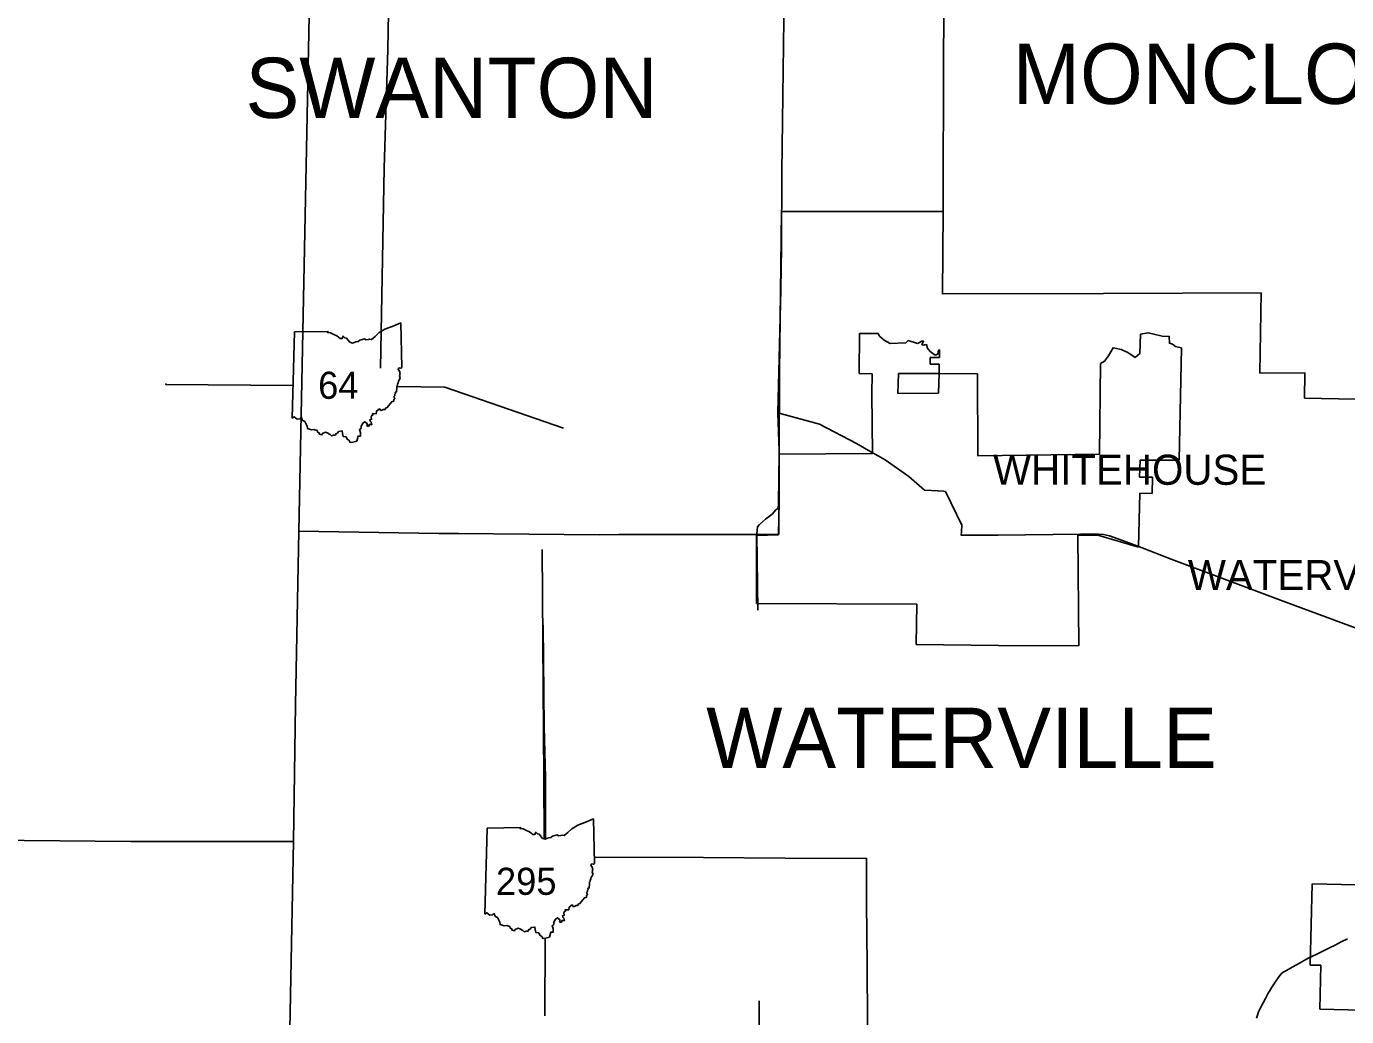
# Model space of a CAD drawing. Extents: x -232 to 448, y 619 to 1059.
# Drawn here: x 68.14 to 113.08, y 864.09 to 897.81 of the extents above; entities that cross this region are included whole.
import ezdxf

# ---------------------------------------------------------------- set-up
doc = ezdxf.new("R2010")
doc.units = 0
doc.layers.add('Default', color=7, linetype='Continuous')

msp = doc.modelspace()

# ---------------------------------------------------------------- linework, layer by layer
at = {"layer": 'Default'}
for p, q in [((77.184, 884.471), (77.266, 887.4)), ((77.184, 884.471), (77.266, 887.4)), ((96.497, 887.343), (96.48, 885.992)), ((97.134, 887.343), (96.497, 887.343)), ((97.182, 887.256), (97.134, 887.343)), ((97.333, 887.121), (97.182, 887.256)), ((97.543, 887.007), (97.333, 887.121)), ((98.155, 887.111), (98.071, 887.035)), ((98.471, 887.009), (98.155, 887.111)), ((98.615, 887.092), (98.471, 887.009)), ((98.678, 887.102), (98.615, 887.092)), ((98.622, 886.958), (98.678, 887.102)), ((98.071, 887.035), (97.543, 887.007)), ((98.681, 886.948), (98.622, 886.958)), ((98.752, 886.97), (98.681, 886.948)), ((98.793, 886.961), (98.752, 886.97)), ((98.801, 886.864), (98.793, 886.961)), ((98.9, 886.735), (98.801, 886.864)), ((99.034, 886.628), (98.9, 886.735)), ((99.085, 886.611), (99.034, 886.628)), ((99.173, 886.651), (99.085, 886.611)), ((99.175, 886.733), (99.173, 886.651)), ((99.223, 886.801), (99.175, 886.733)), ((99.216, 886.535), (99.223, 886.801)), ((98.906, 886.534), (99.216, 886.535)), ((98.906, 886.3), (98.906, 886.534)), ((99.211, 886.3), (98.906, 886.3)), ((99.204, 885.991), (99.211, 886.3)), ((106.469, 882.452), (106.026, 882.454)), ((106.454, 881.901), (106.469, 882.452)), ((106.035, 881.914), (106.454, 881.901)), ((83.743, 867.581), (83.825, 870.51)), ((83.743, 867.581), (83.825, 870.51)), ((111.904, 868.613), (111.837, 865.843)), ((113.904, 868.564), (111.904, 868.613)), ((111.837, 865.843), (112.196, 865.835)), ((112.196, 865.835), (112.16, 864.343)), ((112.16, 864.343), (116.541, 864.237))]:
    msp.add_line(p, q, dxfattribs=at)
for points in [[(99.344, 891.498), (99.352, 896.947), (99.427, 902.322), (99.435, 907.773), (99.476, 913.158)], [(77.412, 880.616), (77.896, 904.964), (77.947, 907.809)], [(93.721, 884.643), (93.821, 888.838), (93.84, 890.285), (93.853, 892.85), (93.98, 902.356)], [(80.187, 886.165), (80.321, 892.983), (80.445, 897.015), (80.493, 899.517)], [(93, 880.507), (93.754, 880.517), (93.773, 886.025), (93.847, 891.503), (99.344, 891.498)], [(127.784, 884.833), (111.649, 885.151), (111.657, 885.999), (110.121, 886.009), (110.165, 888.733), (104.807, 888.708), (99.321, 888.696), (99.344, 891.498)], [(77.266, 887.4), (78.402, 887.419), (78.385, 887.383), (78.492, 887.376), (78.606, 887.313), (78.702, 887.274), (78.82, 887.181), (78.891, 887.182), (78.92, 887.258), (78.974, 887.199), (79.038, 887.189), (79.149, 887.048), (79.241, 887.018), (79.35, 887.066), (79.432, 887.074), (79.492, 887.121), (79.648, 887.162), (79.691, 887.138), (79.774, 887.143), (79.815, 887.161), (79.887, 887.145), (80.014, 887.251), (80.145, 887.377), (80.345, 887.495), (80.645, 887.607), (80.882, 887.708), (80.916, 886.188)], [(77.266, 887.4), (78.402, 887.419), (78.385, 887.383), (78.492, 887.376), (78.606, 887.313), (78.702, 887.274), (78.82, 887.181), (78.891, 887.182), (78.92, 887.258), (78.974, 887.199), (79.038, 887.189), (79.149, 887.048), (79.241, 887.018), (79.35, 887.066), (79.432, 887.074), (79.492, 887.121), (79.648, 887.162), (79.691, 887.138), (79.774, 887.143), (79.815, 887.161), (79.887, 887.145), (80.014, 887.251), (80.145, 887.377), (80.345, 887.495), (80.645, 887.607), (80.882, 887.708), (80.916, 886.188)], [(107.461, 886.861), (107.256, 886.902), (107.146, 886.983), (107.046, 887.019), (107.04, 887.252), (106.794, 887.26), (106.516, 887.33), (106.317, 887.373), (106.06, 887.324), (106.038, 886.664), (105.885, 886.53)], [(105.885, 886.53), (105.634, 886.7), (105.399, 886.805), (105.128, 886.865), (104.968, 886.584), (104.833, 886.407), (104.697, 886.322), (104.671, 883.236)], [(106.026, 882.454), (106.046, 883.035), (107.377, 883.036), (107.461, 886.861)], [(80.916, 886.188), (80.881, 886.166), (80.827, 886.176), (80.79, 886.134), (80.836, 886.063), (80.857, 885.988), (80.838, 885.905), (80.857, 885.836), (80.844, 885.779), (80.81, 885.722), (80.798, 885.668), (80.769, 885.611), (80.771, 885.579), (80.744, 885.554), (80.749, 885.459), (80.735, 885.406), (80.739, 885.36), (80.694, 885.349), (80.705, 885.311), (80.676, 885.282), (80.682, 885.232), (80.65, 885.2), (80.681, 885.136), (80.656, 885.116), (80.635, 885.039), (80.577, 885.023), (80.462, 884.881), (80.421, 884.828), (80.375, 884.814), (80.35, 884.759), (80.294, 884.759), (80.208, 884.721), (80.153, 884.786), (80.056, 884.707), (80.045, 884.616), (79.923, 884.619), (79.928, 884.573), (79.9, 884.559), (79.875, 884.513), (79.89, 884.431), (79.833, 884.41), (79.84, 884.362), (79.876, 884.333), (79.893, 884.242), (79.832, 884.26), (79.782, 884.183), (79.731, 884.201), (79.747, 884.267), (79.661, 884.345), (79.579, 884.282), (79.536, 884.182), (79.536, 884.114), (79.475, 884.074), (79.514, 883.978), (79.507, 883.913), (79.508, 883.851), (79.432, 883.853), (79.385, 883.685)], [(80.916, 886.188), (80.881, 886.166), (80.827, 886.176), (80.79, 886.134), (80.836, 886.063), (80.857, 885.988), (80.838, 885.905), (80.857, 885.836), (80.844, 885.779), (80.81, 885.722), (80.798, 885.668), (80.769, 885.611), (80.771, 885.579), (80.744, 885.554), (80.749, 885.459), (80.735, 885.406), (80.739, 885.36), (80.694, 885.349), (80.705, 885.311), (80.676, 885.282), (80.682, 885.232), (80.65, 885.2), (80.681, 885.136), (80.656, 885.116), (80.635, 885.039), (80.577, 885.023), (80.462, 884.881), (80.421, 884.828), (80.375, 884.814), (80.35, 884.759), (80.294, 884.759), (80.208, 884.721), (80.153, 884.786), (80.056, 884.707), (80.045, 884.616), (79.923, 884.619), (79.928, 884.573), (79.9, 884.559), (79.875, 884.513), (79.89, 884.431), (79.833, 884.41), (79.84, 884.362), (79.876, 884.333), (79.893, 884.242), (79.832, 884.26), (79.782, 884.183), (79.731, 884.201), (79.747, 884.267), (79.661, 884.345), (79.579, 884.282), (79.536, 884.182), (79.536, 884.114), (79.475, 884.074), (79.514, 883.978), (79.507, 883.913), (79.508, 883.851), (79.432, 883.853), (79.385, 883.685)], [(96.48, 885.992), (96.929, 885.978)], [(96.929, 885.978), (96.913, 885.298)], [(97.819, 885.992), (97.801, 885.302)], [(99.204, 885.991), (97.819, 885.992)], [(99.187, 885.314), (99.204, 885.991)], [(104.671, 883.236), (100.522, 883.187), (100.51, 885.97), (99.204, 885.991)], [(77.215, 885.583), (72.885, 885.616), (72.885, 885.648)], [(86.42, 884.126), (82.381, 885.518), (80.744, 885.541)], [(96.913, 885.298), (96.935, 883.259)], [(97.801, 885.302), (99.187, 885.314)], [(79.385, 883.685), (79.253, 883.652), (79.161, 883.633), (79.128, 883.71), (79.062, 883.75), (79.02, 883.827), (78.925, 883.837), (78.903, 883.943), (78.892, 884.029), (78.763, 884.007), (78.727, 883.955), (78.682, 883.941), (78.655, 883.888), (78.592, 883.884), (78.525, 883.859), (78.482, 883.911), (78.372, 883.963), (78.322, 883.989), (78.219, 883.948), (78.197, 883.898), (78.115, 883.92), (78.096, 883.975), (78.046, 883.992), (78.035, 884.05), (77.928, 884.081), (77.847, 884.069), (77.704, 884.116), (77.695, 884.192), (77.646, 884.286), (77.621, 884.351), (77.53, 884.401), (77.511, 884.478), (77.482, 884.475), (77.456, 884.444), (77.355, 884.43), (77.315, 884.461), (77.259, 884.515), (77.184, 884.471)], [(79.385, 883.685), (79.253, 883.652), (79.161, 883.633), (79.128, 883.71), (79.062, 883.75), (79.02, 883.827), (78.925, 883.837), (78.903, 883.943), (78.892, 884.029), (78.763, 884.007), (78.727, 883.955), (78.682, 883.941), (78.655, 883.888), (78.592, 883.884), (78.525, 883.859), (78.482, 883.911), (78.372, 883.963), (78.322, 883.989), (78.219, 883.948), (78.197, 883.898), (78.115, 883.92), (78.096, 883.975), (78.046, 883.992), (78.035, 884.05), (77.928, 884.081), (77.847, 884.069), (77.704, 884.116), (77.695, 884.192), (77.646, 884.286), (77.621, 884.351), (77.53, 884.401), (77.511, 884.478), (77.482, 884.475), (77.456, 884.444), (77.355, 884.43), (77.315, 884.461), (77.259, 884.515), (77.184, 884.471)], [(96.802, 883.37), (96.396, 883.599), (95.133, 884.263), (93.721, 884.643)], [(93.762, 883.348), (93.721, 884.643)], [(93.736, 881.561), (93.764, 883.283), (93.762, 883.348)], [(93.766, 883.238), (93.759, 881.618), (93.736, 880.493)], [(96.935, 883.259), (93.766, 883.238)], [(97.132, 883.184), (96.802, 883.37)], [(99.362, 881.975), (99.158, 881.986), (99.176, 881.989), (98.712, 882.01), (98.172, 882.478), (97.368, 883.051), (97.132, 883.184)], [(99.963, 880.6), (99.982, 880.821), (99.423, 881.972), (99.362, 881.975)], [(105.99, 880.072), (106.035, 881.914)], [(93.004, 880.527), (93.008, 880.652), (93.029, 880.761), (93.094, 880.848), (93.293, 881.029), (93.522, 881.199), (93.647, 881.341), (93.733, 881.404), (93.736, 881.561)], [(77.226, 870.052), (77.294, 874.706), (77.412, 880.616)], [(77.412, 880.616), (82.177, 880.541), (82.845, 880.535), (87.636, 880.498), (88.301, 880.5), (93, 880.507)], [(93.736, 880.493), (92.989, 880.471), (92.995, 878.151)], [(93.033, 877.931), (93.004, 880.5), (93.004, 880.527)], [(104.015, 880.512), (101.219, 880.484), (99.953, 880.484), (99.963, 880.6)], [(103.957, 876.714), (103.924, 880.479), (104.607, 880.485)], [(106.119, 880.048), (105.579, 880.258), (105.003, 880.454), (104.801, 880.501), (104.627, 880.518), (104.015, 880.512)], [(104.607, 880.485), (105.99, 880.072)], [(85.767, 870.139), (85.756, 872.214), (85.699, 879.99)], [(115.438, 876.56), (114.537, 876.899), (111.009, 878.195), (107.105, 879.666), (106.119, 880.048)], [(92.995, 878.151), (98.443, 878.129), (98.426, 876.757)], [(85.805, 870.139), (85.811, 872.224), (85.764, 873.967), (85.745, 876.224), (85.732, 877.414)], [(98.426, 876.757), (101.224, 876.723), (103.957, 876.714)], [(83.825, 870.51), (84.961, 870.529), (84.943, 870.493), (85.051, 870.486), (85.164, 870.423), (85.261, 870.384), (85.379, 870.291), (85.449, 870.292), (85.479, 870.368), (85.533, 870.309), (85.597, 870.299), (85.708, 870.158), (85.799, 870.128), (85.909, 870.176), (85.991, 870.184), (86.05, 870.232), (86.206, 870.272), (86.25, 870.248), (86.332, 870.253), (86.374, 870.271), (86.446, 870.255), (86.573, 870.361), (86.703, 870.487), (86.904, 870.605), (87.204, 870.717), (87.441, 870.818), (87.475, 869.298)], [(83.825, 870.51), (84.961, 870.529), (84.943, 870.493), (85.051, 870.486), (85.164, 870.423), (85.261, 870.384), (85.379, 870.291), (85.449, 870.292), (85.479, 870.368), (85.533, 870.309), (85.597, 870.299), (85.708, 870.158), (85.799, 870.128), (85.909, 870.176), (85.991, 870.184), (86.05, 870.232), (86.206, 870.272), (86.25, 870.248), (86.332, 870.253), (86.374, 870.271), (86.446, 870.255), (86.573, 870.361), (86.703, 870.487), (86.904, 870.605), (87.204, 870.717), (87.441, 870.818), (87.475, 869.298)], [(44.577, 870.248), (49.918, 870.254), (71.698, 870.05), (77.226, 870.052)], [(76.671, 842.765), (76.826, 849.139), (77.226, 870.052)], [(87.475, 869.298), (87.44, 869.277), (87.386, 869.287), (87.349, 869.244), (87.394, 869.173), (87.416, 869.098), (87.397, 869.015), (87.415, 868.947), (87.403, 868.889), (87.368, 868.833), (87.357, 868.778), (87.328, 868.721), (87.33, 868.689), (87.302, 868.664), (87.307, 868.569), (87.293, 868.516), (87.298, 868.471), (87.253, 868.459), (87.263, 868.421), (87.235, 868.392), (87.241, 868.342), (87.208, 868.31), (87.24, 868.247), (87.215, 868.226), (87.194, 868.149), (87.136, 868.133), (87.02, 867.991), (86.98, 867.938), (86.934, 867.924), (86.908, 867.869), (86.852, 867.869), (86.767, 867.831), (86.712, 867.897), (86.615, 867.817), (86.604, 867.726), (86.481, 867.729), (86.486, 867.683), (86.459, 867.669), (86.434, 867.623), (86.449, 867.541), (86.391, 867.52), (86.398, 867.472), (86.435, 867.443), (86.451, 867.352), (86.39, 867.37), (86.34, 867.294), (86.289, 867.312), (86.306, 867.377), (86.219, 867.455), (86.138, 867.392), (86.095, 867.292), (86.094, 867.225), (86.033, 867.184), (86.072, 867.089), (86.065, 867.023), (86.067, 866.961), (85.99, 866.963), (85.944, 866.795)], [(87.475, 869.298), (87.44, 869.277), (87.386, 869.287), (87.349, 869.244), (87.394, 869.173), (87.416, 869.098), (87.397, 869.015), (87.415, 868.947), (87.403, 868.889), (87.368, 868.833), (87.357, 868.778), (87.328, 868.721), (87.33, 868.689), (87.302, 868.664), (87.307, 868.569), (87.293, 868.516), (87.298, 868.471), (87.253, 868.459), (87.263, 868.421), (87.235, 868.392), (87.241, 868.342), (87.208, 868.31), (87.24, 868.247), (87.215, 868.226), (87.194, 868.149), (87.136, 868.133), (87.02, 867.991), (86.98, 867.938), (86.934, 867.924), (86.908, 867.869), (86.852, 867.869), (86.767, 867.831), (86.712, 867.897), (86.615, 867.817), (86.604, 867.726), (86.481, 867.729), (86.486, 867.683), (86.459, 867.669), (86.434, 867.623), (86.449, 867.541), (86.391, 867.52), (86.398, 867.472), (86.435, 867.443), (86.451, 867.352), (86.39, 867.37), (86.34, 867.294), (86.289, 867.312), (86.306, 867.377), (86.219, 867.455), (86.138, 867.392), (86.095, 867.292), (86.094, 867.225), (86.033, 867.184), (86.072, 867.089), (86.065, 867.023), (86.067, 866.961), (85.99, 866.963), (85.944, 866.795)], [(98.376, 854.972), (97.05, 856.338), (95.842, 857.594), (95.48, 857.981), (95.944, 858.458), (96.532, 859.046), (96.785, 859.297), (96.783, 860.669), (96.783, 861.849), (96.769, 863.888), (96.752, 865.855), (96.733, 867.977), (96.736, 869.474), (93.965, 869.484), (91.184, 869.502), (87.47, 869.512)], [(85.944, 866.795), (85.811, 866.763), (85.719, 866.743), (85.687, 866.82), (85.621, 866.86), (85.578, 866.937), (85.484, 866.947), (85.461, 867.053), (85.451, 867.139), (85.321, 867.118), (85.286, 867.065), (85.24, 867.051), (85.214, 866.998), (85.151, 866.994), (85.084, 866.969), (85.04, 867.021), (84.93, 867.073), (84.881, 867.1), (84.778, 867.058), (84.756, 867.009), (84.673, 867.03), (84.654, 867.085), (84.604, 867.102), (84.593, 867.16), (84.487, 867.191), (84.406, 867.179), (84.262, 867.226), (84.253, 867.303), (84.205, 867.396), (84.179, 867.461), (84.088, 867.511), (84.07, 867.588), (84.041, 867.586), (84.015, 867.554), (83.914, 867.54), (83.874, 867.571), (83.817, 867.625), (83.743, 867.581)], [(85.944, 866.795), (85.811, 866.763), (85.719, 866.743), (85.687, 866.82), (85.621, 866.86), (85.578, 866.937), (85.484, 866.947), (85.461, 867.053), (85.451, 867.139), (85.321, 867.118), (85.286, 867.065), (85.24, 867.051), (85.214, 866.998), (85.151, 866.994), (85.084, 866.969), (85.04, 867.021), (84.93, 867.073), (84.881, 867.1), (84.778, 867.058), (84.756, 867.009), (84.673, 867.03), (84.654, 867.085), (84.604, 867.102), (84.593, 867.16), (84.487, 867.191), (84.406, 867.179), (84.262, 867.226), (84.253, 867.303), (84.205, 867.396), (84.179, 867.461), (84.088, 867.511), (84.07, 867.588), (84.041, 867.586), (84.015, 867.554), (83.914, 867.54), (83.874, 867.571), (83.817, 867.625), (83.743, 867.581)], [(85.786, 864.111), (85.794, 866.759)], [(110.013, 864.033), (110.046, 864.141), (110.083, 864.254), (110.157, 864.413), (110.232, 864.556), (110.314, 864.708), (110.397, 864.861), (110.486, 865.016), (110.579, 865.156), (110.667, 865.29), (110.745, 865.406), (110.804, 865.489), (110.85, 865.546), (110.914, 865.599), (111.01, 865.652), (111.113, 865.708), (111.229, 865.774), (111.368, 865.848), (111.548, 865.956), (111.77, 866.073), (112.045, 866.206), (112.264, 866.316), (112.492, 866.433), (112.682, 866.526), (112.889, 866.63), (113.102, 866.735)], [(93.142, 850.111), (93.087, 854.797), (93.087, 858.634), (93.078, 861.815), (93.087, 864.628)]]:
    msp.add_lwpolyline(points, dxfattribs=at)

# ---------------------------------------------------------------- texts
for s, height, p in [('MONCLOVA', 2.052, (101.717, 895.168)), ('SWANTON', 2.052, (75.598, 894.687)), ('64', 0.9234, (78.07, 885.124)), ('WHITEHOUSE', 1.026, (101.042, 882.197)), ('WATERVILLE', 1.026, (107.673, 878.609)), ('WATERVILLE', 2.052, (91.28, 872.552)), ('295', 0.9234, (84.123, 868.234))]:
    msp.add_text(s, height=height, dxfattribs=at).set_placement(p)

doc.saveas('drawing.dxf')
